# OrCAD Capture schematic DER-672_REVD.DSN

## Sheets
1 PAGE1: size Custom; title: DER-672; rev: D
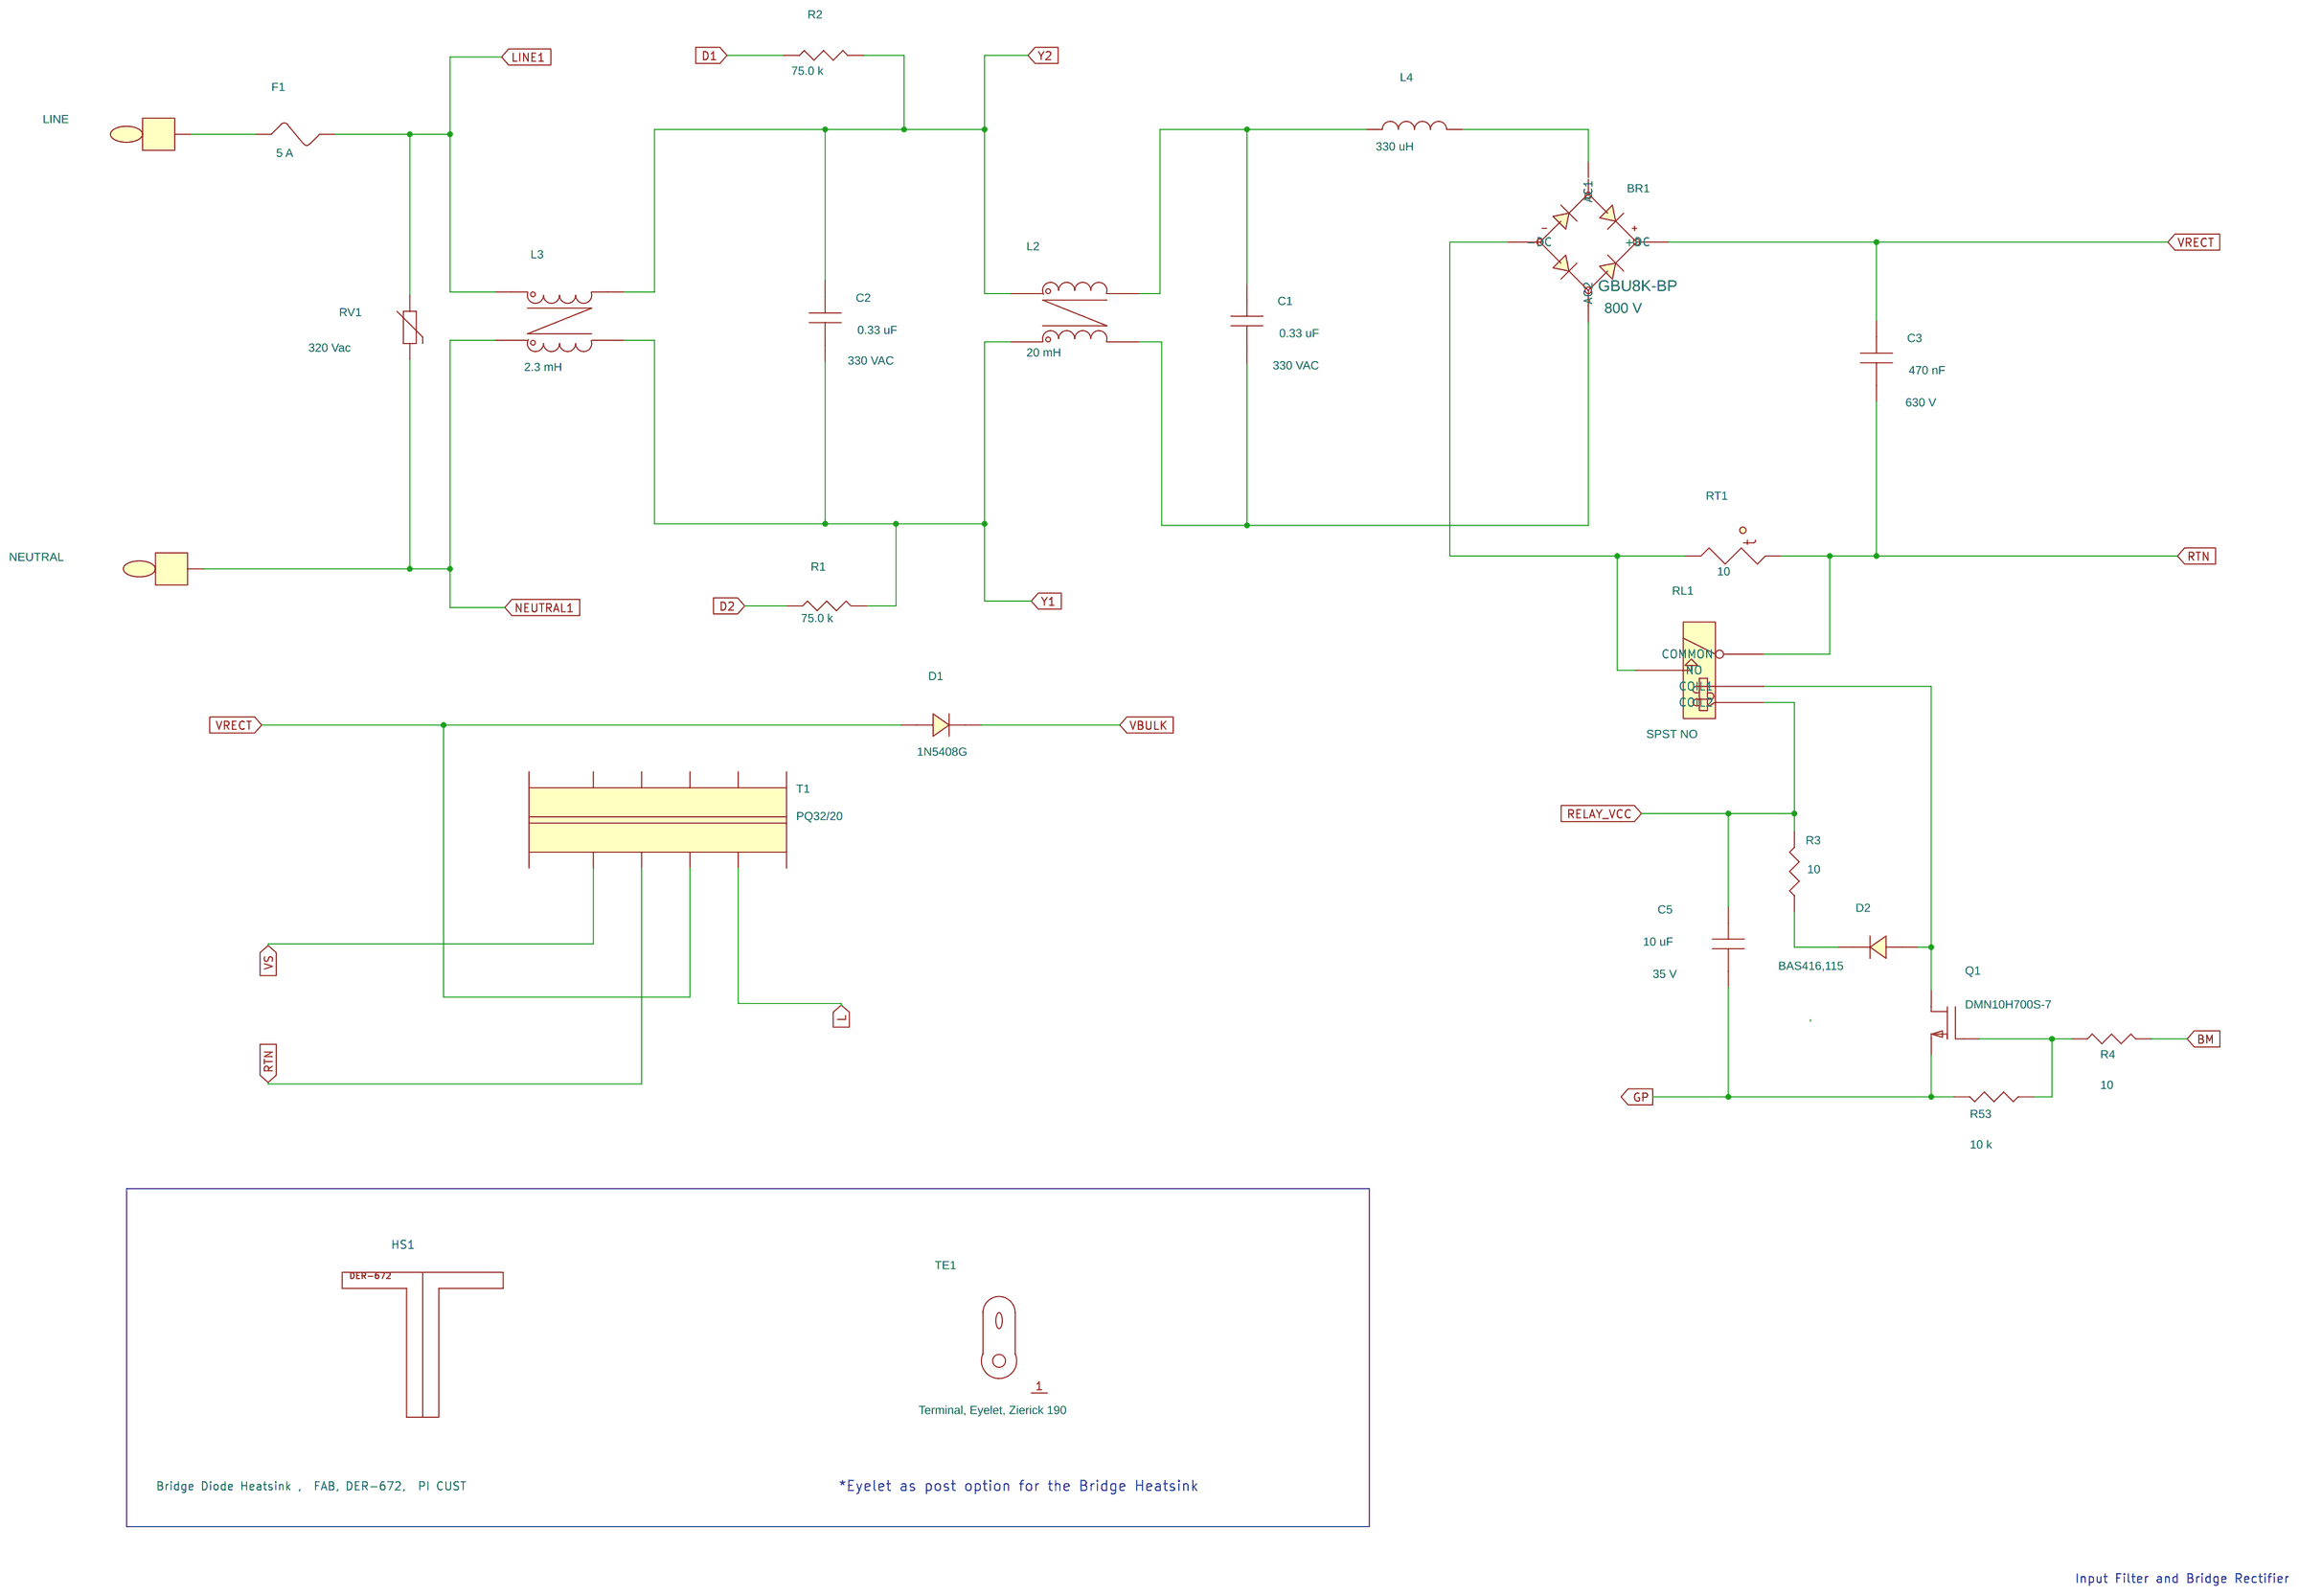
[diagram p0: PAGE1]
2 PAGE2: size B
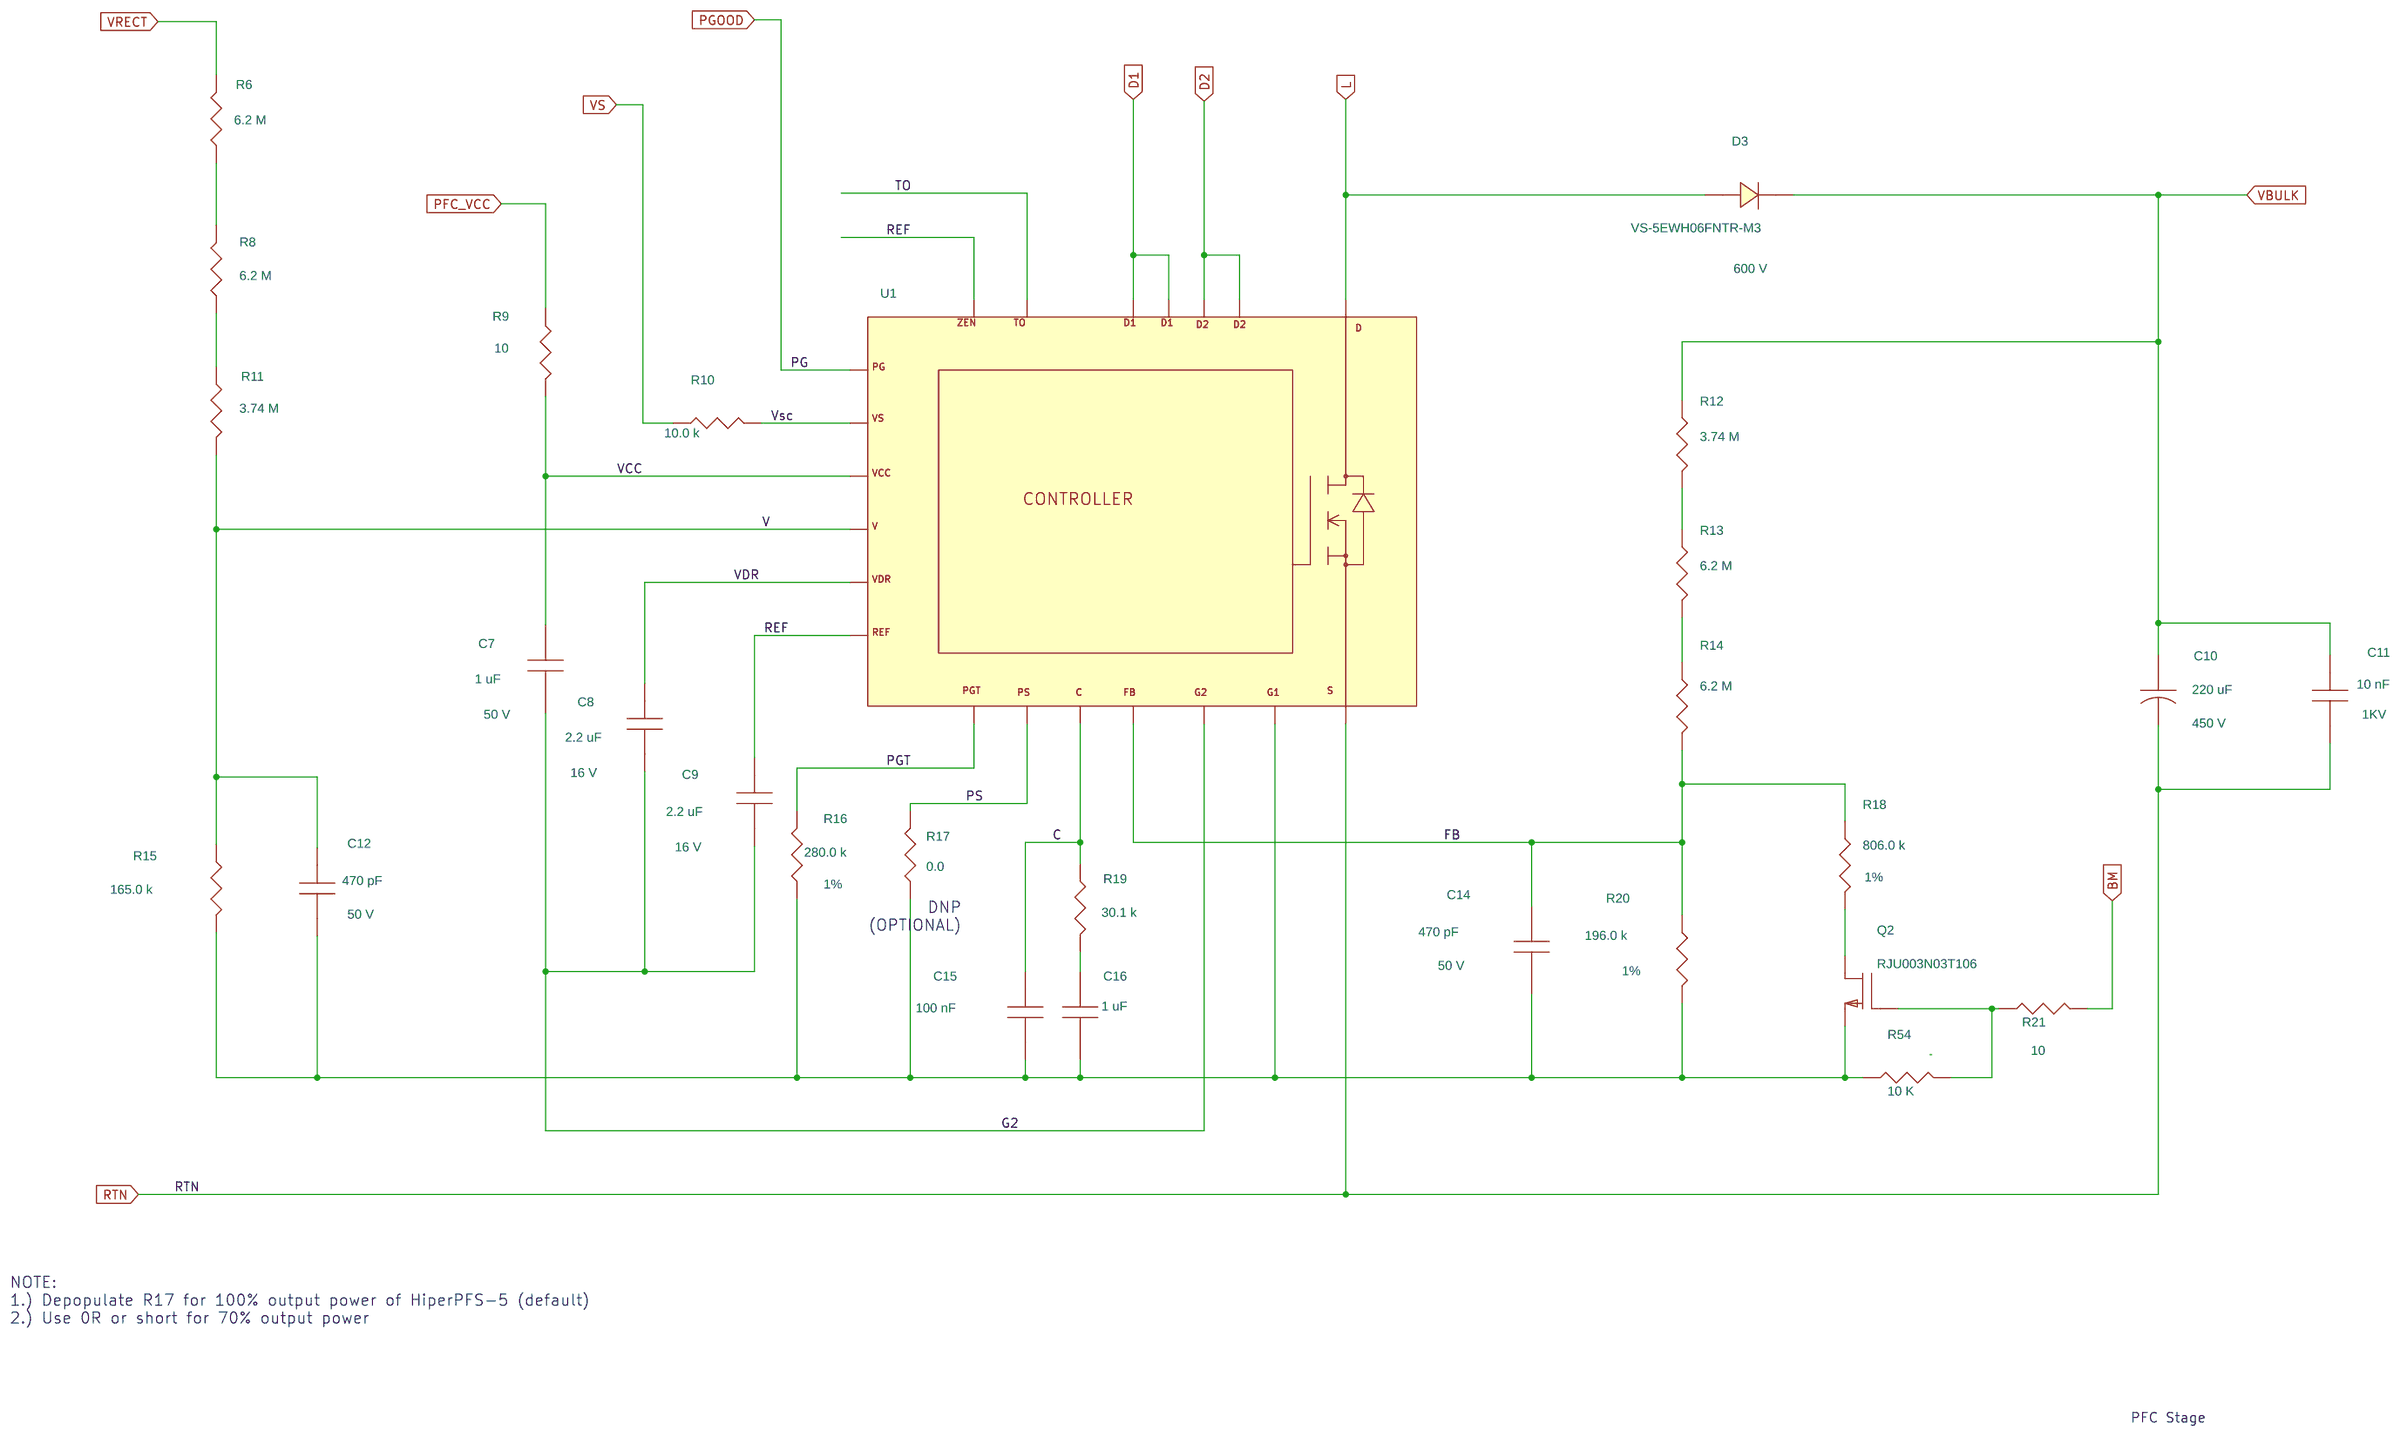
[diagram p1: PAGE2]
3 PAGE3: size Custom
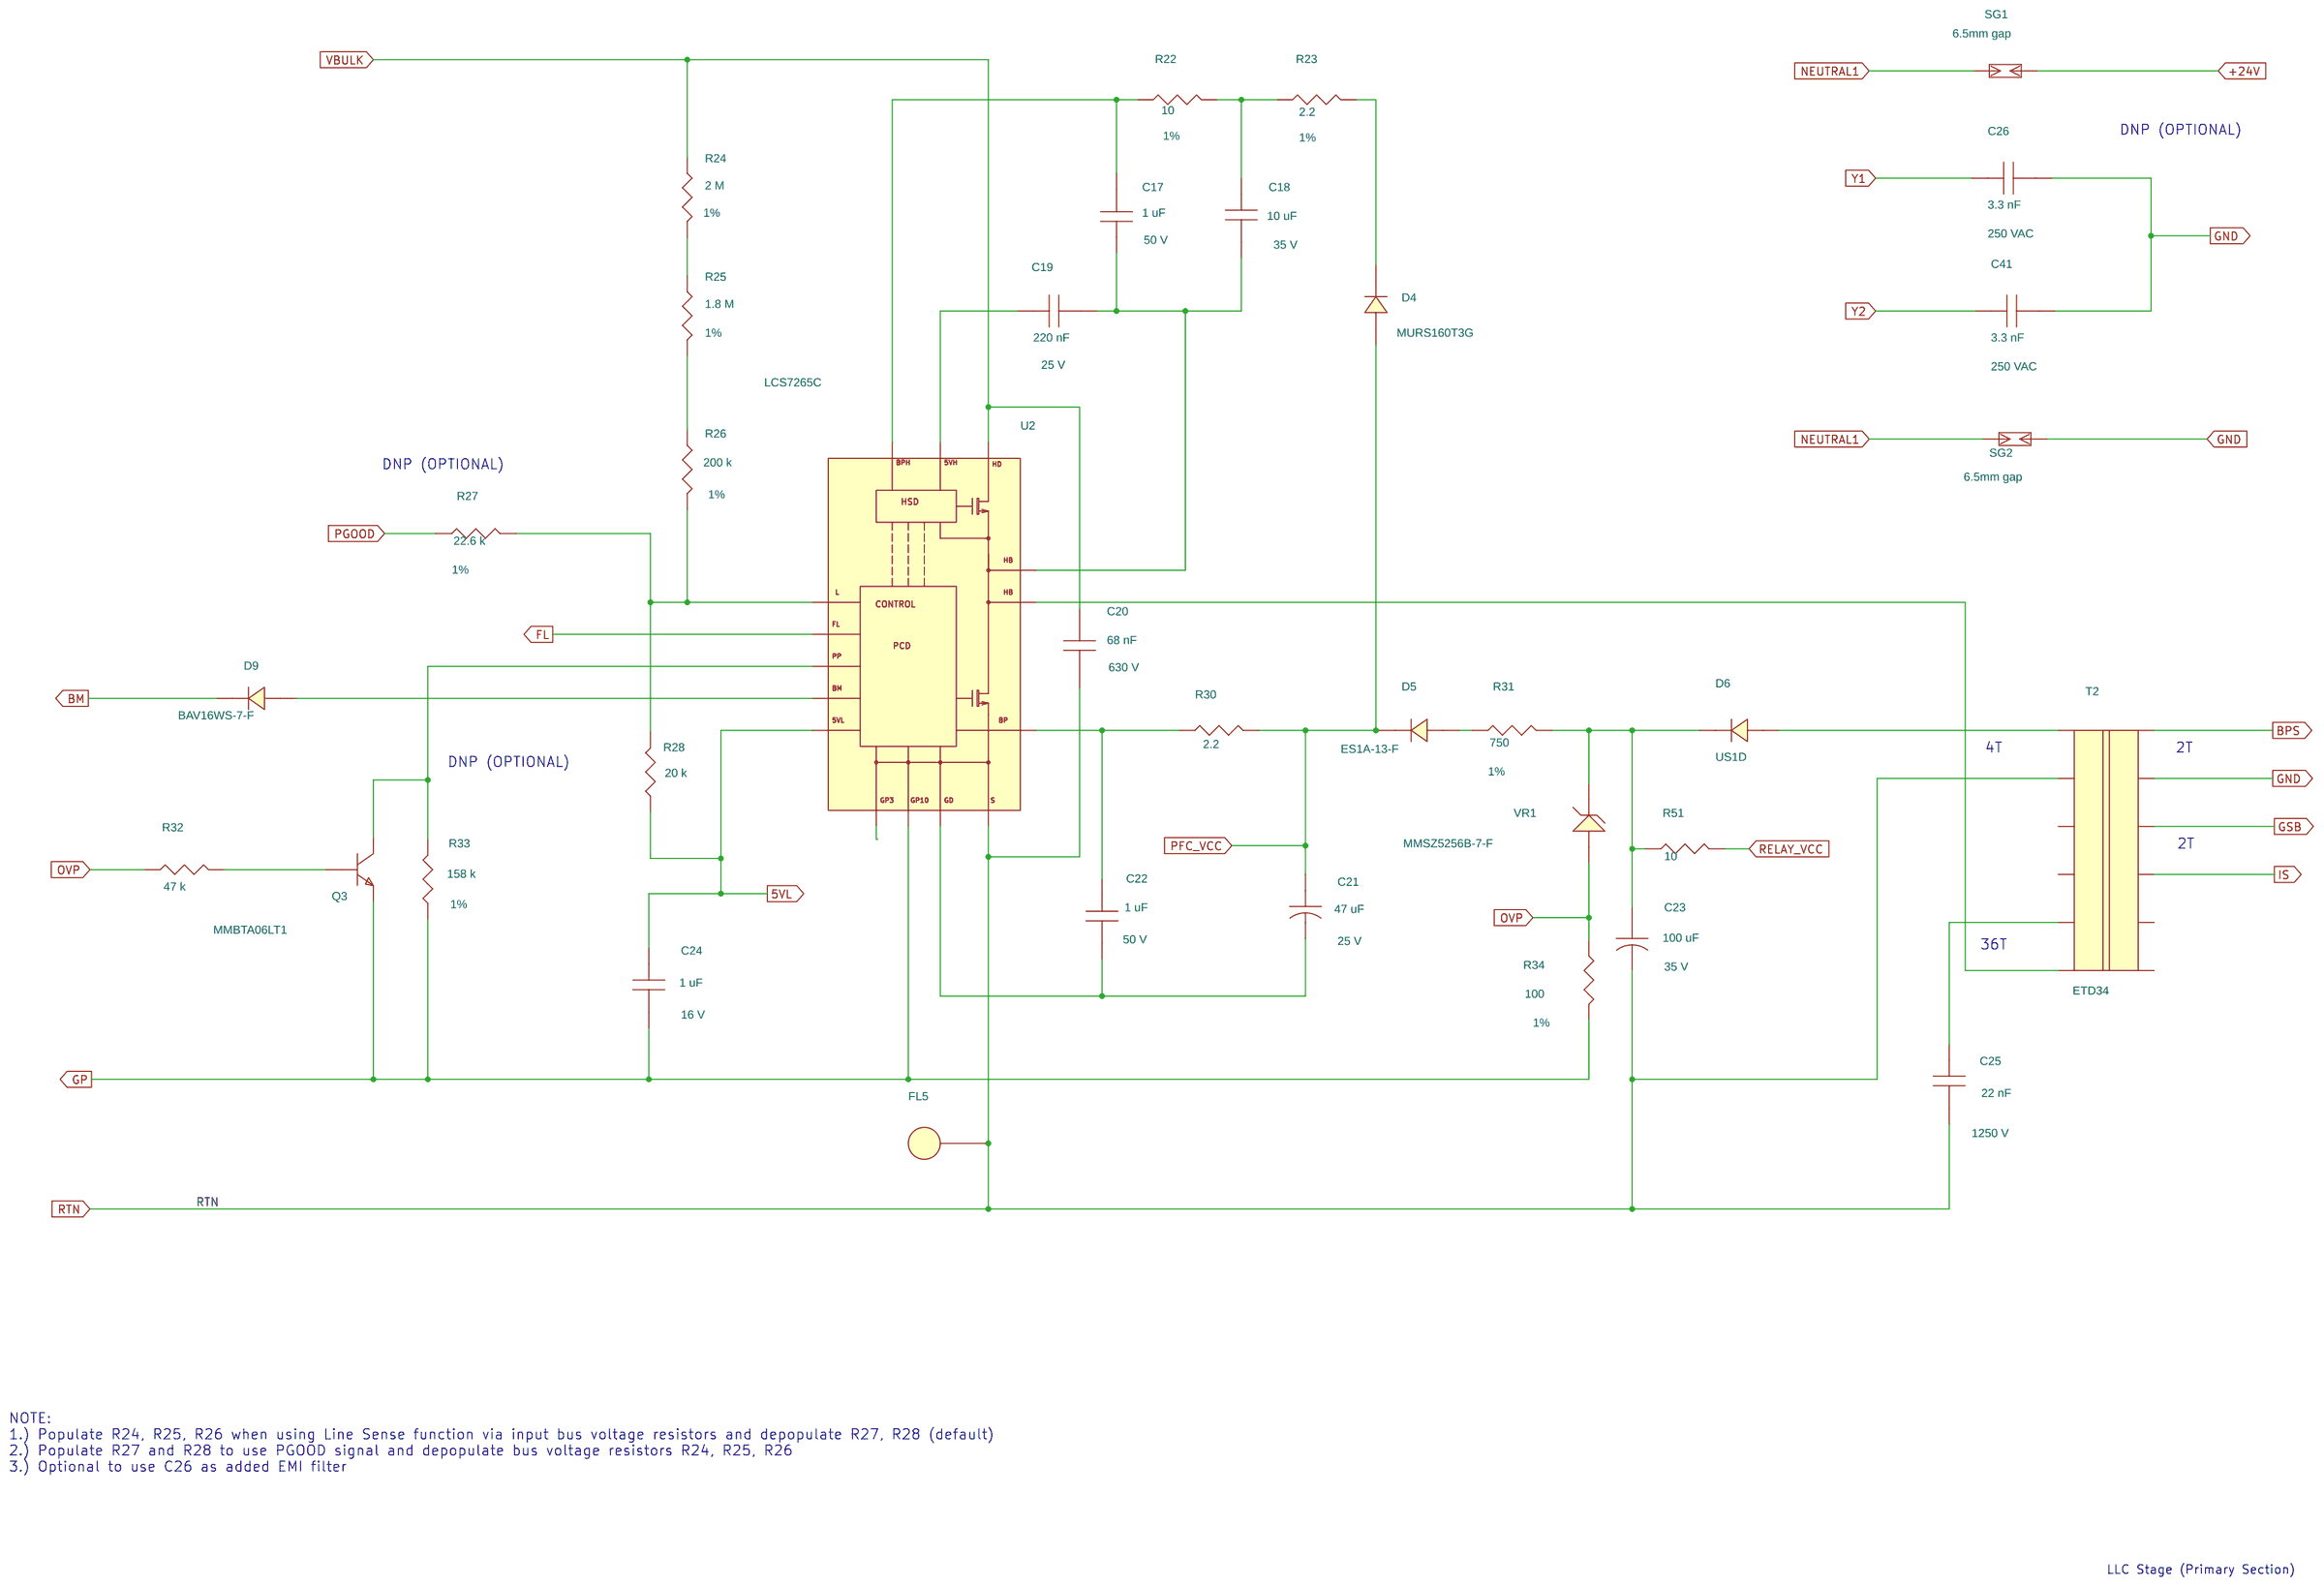
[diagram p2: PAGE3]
4 PAGE4: size Custom
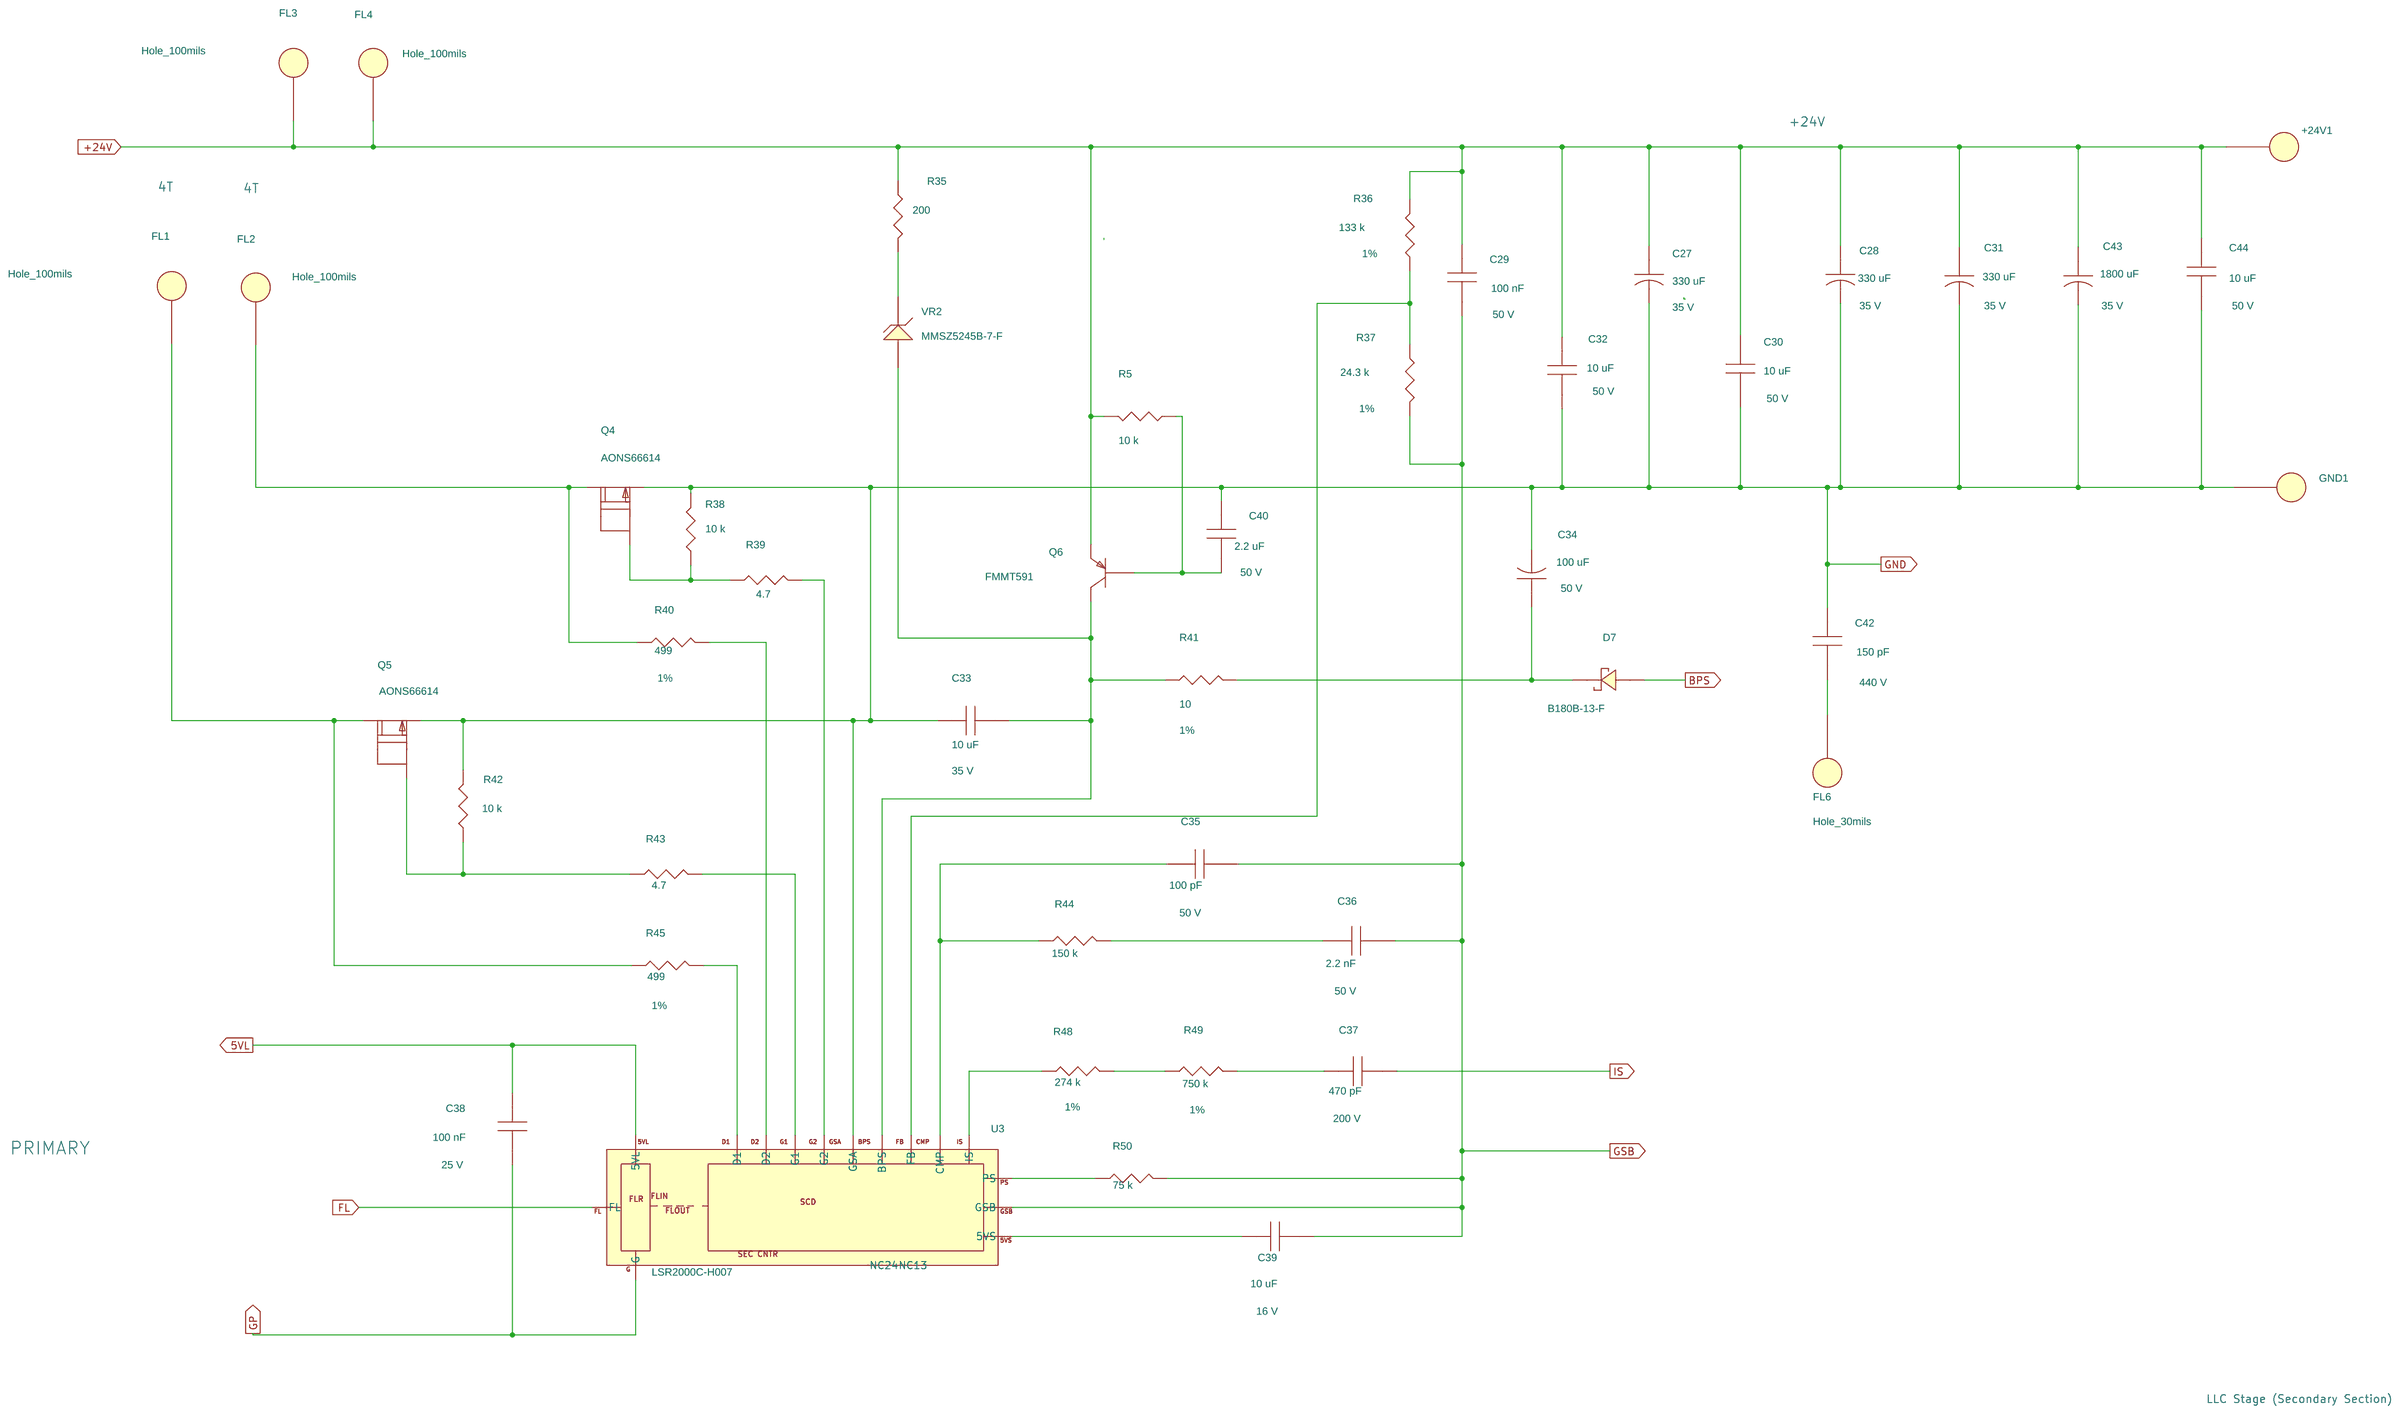
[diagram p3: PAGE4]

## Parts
sheet PAGE1
BR1  GBU8K-BP  [pidaxbridgegbu8]
C1  0.33 uF  [pi_np_caprad709x354ls590d050]
C2  0.33 uF  [pi_np_caprad709x354ls590d050]
C3  470 nF  [pinpcaprad760x450675040]
C5  10 uF  [pismc0805]
D1  1N5408G  [pidv300x200x060do15d0201ad]
D2  BAS416,115  [pismdsod323]
F1  5 A  [pi_tr5_submin_fuse]
HS1  Bridge Diode Heatsink ,  FAB, DER-672,  PI CUST  [PI_hs_0P_Bridge_DER-672]
L2  20 mH  [pi4p28x19p5x20lsd60]
L3  2.3 mH  [pi4p21p7x11p5d60]
L4  330 uH  [pi_toroid_2p_550x950_ls480_d050]
LINE  WHT  [pitpkeystone125x125]
NEUTRAL  YEL  [pitpkeystone125x125]
Q1  DMN10H700S-7  [pismsot23123_1]
R1  75.0 k  [pismr1206]
R2  75.0 k  [pismr1206]
R3  10  [pismr0603]
R4  10  [pismr0603]
R53  10 k  [pismr0603]
RL1  SPST NO  [pi_relay1]
RT1  10  [pi_rad770x220ls330d052]
RV1  320 Vac  [pidisc675x225ls335x140040]
T1  PQ32/20  [pi_bobbin_bpq32_20_12p]
TE1  Terminal, Eyelet, Zierick 190  [pi_zierick190_eyelet]
sheet PAGE2
C7  1 uF  [pismc0603]
C8  2.2 uF  [pismc0402]
C9  2.2 uF  [pismc0402]
C10  220 uF  [pipolcapclyd25mm10mmls080]
C11  10 nF  [pismc1812]
C12  470 pF  [pismr0402]
C14  470 pF  [pismr0402]
C15  100 nF  [pismr0402]
C16  1 uF  [pismr0402]
D3  VS-5EWH06FNTR-M3  [pi_sm_to252_dpak]
Q2  RJU003N03T106  [pismsot323]
R6  6.2 M  [pismr1206]
R8  6.2 M  [pismr1206]
R9  10  [pismr0603]
R10  10.0 k  [pismr0402]
R11  3.74 M  [pismr1206]
R12  3.74 M  [pismr1206]
R13  6.2 M  [pismr1206]
R14  6.2 M  [pismr1206]
R15  165.0 k  [pismr0402]
R16  280.0 k  [pismr0402]
R17  0.0  [pismr0402]
R18  806.0 k  [pismr0402]
R19  30.1 k  [pismr0402]
R20  196.0 k  [pismr0402]
R21  10  [pismr0603]
R54  10 K  [pismr0402]
U1  PFGCZ  [inSOP-T28F]
sheet PAGE3
C17  1 uF  [pismc0805]
C18  10 uF  [pismc0805]
C19  220 nF  [pismc0805]
C20  68 nF  [pinpcaprad760x250590040]
C21  47 uF  [pipolcapclyd200ls80030]
C22  1 uF  [pismc0805]
C23  100 uF  [pipolcapcyld250ls100030]
C24  1 uF  [pismc0603]
C25  22 nF  [pinpxcaprad720x340590040]
C26  3.3 nF  [pinpycaprad540x290ls400040]
C41  3.3 nF  [pinpycaprad540x290ls400040]
D4  MURS160T3G  [pismsmb]
D5  ES1A-13-F  [pismdo214ac12]
D6  US1D  [pismdsma]
D9  BAV16WS-7-F  [pismsod323]
FL5  Hole_30mils  [pi_hole_30mil]
Q3  MMBTA06LT1  [pismsot23123_1]
R22  10  [pismr0603]
R23  2.2  [pismr0603]
R24  2 M  [pismr0805]
R25  1.8 M  [pismr0805]
R26  200 k  [pismr0805]
R27  22.6 k  [pismr0603]
R28  20 k  [pismr0603]
R30  2.2  [pismr0805]
R31  750  [pismr1206]
R32  47 k  [pismr0603]
R33  158 k  [pismr0603]
R34  100  [pismr0603]
R51  10  [pismr1206]
SG1  6.5mm gap  [PI_SPARK_GAP_6p5MM]
SG2  6.5mm gap  [PI_SPARK_GAP_6p5MM]
T2  ETD34  [pi_bobbin_etd34_12p_cutout]
U2  LCS7265C  [pi_ic_insop_24C_1]
VR1  MMSZ5256B-7-F  [pi_sm_sod-123_12]
sheet PAGE4
+24V1  Hole_100mils  [pi_hole_100mil]
C27  330 uF  [pipolcapcyld400ls200040]
C28  330 uF  [pipolcapcyld400ls200040]
C29  100 nF  [pismc0603]
C30  10 uF  [pismc1206]
C31  330 uF  [pipolcapcyld400ls200040]
C32  10 uF  [pismc1206]
C33  10 uF  [pismc0805]
C34  100 uF  [pipolcapclyd320ls140030]
C35  100 pF  [pismc0603]
C36  2.2 nF  [pismc0603]
C37  470 pF  [pismc0805]
C38  100 nF  [pismc0603]
C39  10 uF  [pismc0805]
C40  2.2 uF  [pismc0805]
C42  150 pF  [pinpcaprad6p5x5p5x10mmlsd030]
C43  1800 uF  [pipolcapclyd630ls300040]
C44  10 uF  [pismc1206]
D7  B180B-13-F  [pismdo214aa12]
FL1  Hole_100mils  [pi_hole_100mil]
FL2  Hole_100mils  [pi_hole_100mil]
FL3  Hole_100mils  [pi_hole_100mil]
FL4  Hole_100mils  [pi_hole_100mil]
FL6  Hole_30mils  [pi_hole_30mil]
GND1  Hole_100mils  [pi_hole_100mil]
Q4  AONS66614  [pismpqfn5x6b]
Q5  AONS66614  [pismpqfn5x6b]
Q6  FMMT591  [pismsot23123_1]
R5  10 k  [pismr0603]
R35  200  [pismr0805]
R36  133 k  [pismr0603]
R37  24.3 k  [pismr0603]
R38  10 k  [pismr0603]
R39  4.7  [pismr0603]
R40  499  [pismr0603]
R41  10  [pismr1206]
R42  10 k  [pismr0603]
R43  4.7  [pismr0603]
R44  150 k  [pismr0603]
R45  499  [pismr0603]
R48  274 k  [pismr0603]
R49  750 k  [pismr0805]
R50  75 k  [pismr0603]
U3  LSR2000C-H007  [pi_ic_insop_24D]
VR2  MMSZ5245B-7-F  [pi_sm_sod-123_12]

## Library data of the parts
BR1 = DISCRETE_BRIDGE_+~~-: ALT_SYMBOLS: pidaxbridgegbu8_horz; Disp_Voltage: 800 V; FPLIST: pidaxbridgegbu8,pidaxbridgegbu8_horz; Part Number: 15-00347-00
C1 C2 = CAP_NP: Disp_Voltage: 330 VAC; Part Number: 20-08966-00; Voltage: 330 VAC
C3 = CAP_NP: Disp_Voltage: 630 V; Part Number: 20-00765-00; Voltage: 630 V
C5 C18 C33 = CAP_NP: ALT_SYMBOLS: Unisem_RMCF0805UL,CC0805,pismc0805_1; Disp_Voltage: 35 V; FPLIST: pismc0805,Unisem_RMCF0805UL,CC0805,pismc0805_1; Part Number: 20-01692-00; Voltage: 35 V
D1 = DIODE: ALT_SYMBOLS: pidv300x472x060do14wbead,pidax800x225060do15do201ad,pidv300x200x060do14wbead; FPLIST: pidv300x200x060do15d0201ad,pidv300x472x060do14wbead,pidax800x225060do15do201ad,pidv300x200x060do14wbead; Part Number: 15-01651-00
D2 = DIODE: Part Number: 15-01164-00
F1 = FUSE: Part Number: 40-00005-00
HS1 = hs_0P_Bridge_DER672: Part Number: 61-00318-01
L2 = TORRID_4P_14_23: Part Number: 32-00436-00
L3 = TORRID_4P_14_23: Part Number: 32-00437-00
L4 = INDUCTOR: Part Number: 32-00295-00
LINE = TESTPOINT: Part Number: 35-00044-00
NEUTRAL = TESTPOINT: Part Number: 35-00046-00
Q1 = FET_N_GSD: Part Number: 50-00416-00
R1 R2 = R: Disp_Tol: 1%; Part Number: 05-00373-00
R3 R4 R9 R21 = R: Disp_Tol: 1%; Part Number: 05-00886-00; ROOM: 2
R5 R38 R42 R53 = R: Part Number: 05-01712-00; ROOM: 2
RL1 = RELAY_SPST_NO_1634: Part Number: 66-00378-00
RT1 = THERMISTOR: Part Number: 90-00019-00
RV1 = VARISTOR: Part Number: 85-00009-00
T1 = BPQ32_20_12P_GENERIC: Part Number: 25-00077-00
TE1 = TERM_EYLT: Part Number: 60-00016-00
C7 = CAP_NP: Disp_Voltage: 50 V; Part Number: 20-09159-00; ROOM: 2; Voltage: 50 V
C8 C9 = CAP_NP: ALT_SYMBOLS: pismr0402_1; Disp_Voltage: 16 V; FPLIST: pismc0402,pismr0402_1; Part Number: 20-09202-00; ROOM: 2; Voltage: 16 V
C10 = CAP_POL: ALT_SYMBOLS: pipcap25h40x10mmls080H; Disp_Voltage: 450 V; FPLIST: pipolcapclyd25mm10mmls080,pipcap25h40x10mmls080H; Part Number: 20-01767-00; Voltage: 450 V
C11 = CAP_NP: Disp_Voltage: 1KV; Part Number: 20-00846-00; Voltage: 1KV
C12 C14 = CAP_NP: ALT_SYMBOLS: pismr0402_1; Disp_Voltage: 50 V; FPLIST: pismr0402,pismr0402_1; Part Number: 20-09060-00; ROOM: 2; Voltage: 50 V
C15 = CAP_NP: ALT_SYMBOLS: pismr0402_1; Disp_Voltage: 16 V; FPLIST: pismr0402,pismr0402_1; Part Number: 20-08759-00; ROOM: 2; Voltage: 16 V
C16 = CAP_NP: ALT_SYMBOLS: pismr0402_1; Disp_Voltage: 25 V; FPLIST: pismr0402,pismr0402_1; Part Number: 20-09151-00; ROOM: 2; Voltage: 25 V
D3 = DIODE_DPAK: Disp_Voltage: 600 V; Part Number: 15-01746-00
Q2 = FET_N_SGD: Part Number: 50-00177-00
R6 R8 R13 = R: Part Number: 05-01440-00; ROOM: 2
R10 = R: ALT_SYMBOLS: pismr0402_1; Disp_Tol: 1%; FPLIST: pismr0402,pismr0402_1; Part Number: 05-05935-00; ROOM: 2
R11 R12 = R: Part Number: 05-05572-00; ROOM: 2
R14 = R: Disp_Tol: 1%; Part Number: 05-05567-00; ROOM: 2
R15 = R: Disp_Tol: 1%; Part Number: 05-06059-00; ROOM: 2
R16 = R: Disp_Tol: 1%; Part Number: 05-06083-00; ROOM: 2
R17 = R: Part Number: 05-06420-00; ROOM: 2
R18 = R: Disp_Tol: 1%; Part Number: 05-06136-00; ROOM: 2
R19 = R: Disp_Tol: 1%; Part Number: 05-05984-00; ROOM: 2
R20 = R: Disp_Tol: 1%; Part Number: 05-06065-00; ROOM: 2
R54 = R: Part Number: 05-03488-00; ROOM: 2
U1 = PFSGaN_InSOP-T28F28: Part Number: 10-01271-00
C17 = CAP_NP: Disp_Voltage: 50 V; Part Number: 20-09156-00; Voltage: 50 V
C19 = CAP_NP: Disp_Voltage: 25 V; Part Number: 20-00237-00; Voltage: 25 V
C20 = CAP_NP: Disp_Voltage: 630 V; Part Number: 20-00399-00; Voltage: 630 V
C21 = CAP_POL: ALT_SYMBOLS: pipolcapclyd200ls80030h; Disp_Voltage: 25 V; FPLIST: pipolcapclyd200ls80030,pipolcapclyd200ls80030h; Part Number: 20-00026-00; Voltage: 25 V
C22 = CAP_NP: Disp_Voltage: 50 V; Part Number: 20-09156-00; ROOM: 1; Voltage: 50 V
C23 = CAP_POL: ALT_SYMBOLS: pipolcapclyd250ls100d30h590; Disp_Voltage: 35 V; FPLIST: pipolcapcyld250ls100030,pipolcapclyd250ls100d30h590; Part Number: 20-00117-00; Voltage: 35 V
C24 = CAP_NP: Disp_Voltage: 16 V; Part Number: 20-01020-00; ROOM: 1; Voltage: 16 V
C25 = CAP_NP: Disp_Voltage: 1250 V; Part Number: 20-00722-00; Voltage: 1250 V
C26 C41 = CAP_NP: ALT_SYMBOLS: pinpycaprad540x290ls400040h; Disp_Voltage: 250 VAC; FPLIST: pinpycaprad540x290ls400040,pinpycaprad540x290ls400040h; Part Number: 20-00377-00; Voltage: 250 VAC
D4 = DIODE: Part Number: 15-00487-00; ROOM: 1
D5 = DIODE: Part Number: 15-00351-00
D6 = DIODE: Part Number: 15-00492-00
D9 = DIODE: Part Number: 15-00850-00; ROOM: 1
FL5 FL6 = FlyingLead: Part Number: 35-00284-00
Q3 = NPN_BEC: Part Number: 55-00030-00
R22 = R: Disp_Tol: 1%; Part Number: 05-00886-00
R23 = R: Disp_Tol: 1%; Part Number: 05-01278-00
R24 = R: Disp_Tol: 1%; Part Number: 05-00883-00; ROOM: 1
R25 = R: Disp_Tol: 1%; Part Number: 05-00882-00; ROOM: 1
R26 = R: ALT_SYMBOLS: Unisem_RMCF0805UL; Disp_Tol: 1%; FPLIST: pismr0805,Unisem_RMCF0805UL; Part Number: 05-00809-00
R27 = R: Disp_Tol: 1%; Part Number: 05-03218-00; ROOM: 1
R28 = R: Part Number: 05-01719-00; ROOM: 1
R30 = R: Part Number: 05-01455-00
R31 = R: Disp_Tol: 1%; Part Number: 05-00181-00
R32 = R: Part Number: 05-01728-00
R33 = R: Disp_Tol: 1%; Part Number: 05-01193-00; ROOM: 1
R34 = R: Disp_Tol: 1%; Part Number: 05-06490-00
R41 R51 = R: Disp_Tol: 1%; Part Number: 05-00001-00
SG1 SG2 = SPARK_GAP: Part Number: 66-00355-00
T2 = BETD34_12P_GENERIC: Part Number: 25-01048-00
U2 = HiperLCS-SR_A_INSOP24C_5: Part Number: 10-01120-00
VR1 = DIODE_ZENER: Part Number: 15-01096-00
+24V1 FL1-FL4 GND1 = FlyingLead: Part Number: 35-00432-00; ROOM: 2
C27 C28 C31 = CAP_POL: Disp_Voltage: 35 V; Part Number: 20-01364-00; Voltage: 35 V
C29 = CAP_NP: Disp_Voltage: 50 V; Part Number: 20-01693-00; Voltage: 50 V
C30 C32 C44 = CAP_NP: ALT_SYMBOLS: pismc1206_1; Disp_Voltage: 50 V; FPLIST: pismc1206,pismc1206_1; Part Number: 20-08995-00; Voltage: 50 V
C34 = CAP_POL: ALT_SYMBOLS: pipolcapclyd320ls140030430h; Disp_Voltage: 50 V; FPLIST: pipolcapclyd320ls140030,pipolcapclyd320ls140030430h,pipolcapclyd320ls140030430h; Part Number: 20-00058-00; Voltage: 50 V
C35 = CAP_NP: Disp_Voltage: 50 V; Part Number: 20-01025-00; ROOM: 2; Voltage: 50 V
C36 = CAP_NP: Disp_Voltage: 50 V; Part Number: 20-08677-00; ROOM: 2; Voltage: 50 V
C37 = CAP_NP: Disp_Voltage: 200 V; Part Number: 20-01187-00; ROOM: 2; Voltage: 200 V
C38 = CAP_NP: Disp_Voltage: 25 V; Part Number: 20-00528-00; Voltage: 25 V
C39 = CAP_NP: ALT_SYMBOLS: Unisem_RMCF0805UL; Disp_Voltage: 16 V; FPLIST: pismc0805,Unisem_RMCF0805UL; Part Number: 20-08964-00; Voltage: 16 V
C40 = CAP_NP: Disp_Voltage: 50 V; Part Number: 20-09011-00; ROOM: 2; Voltage: 50 V
C42 = CAP_NP: Disp_Voltage: 440 V; Part Number: 20-02055-00; Voltage: 440 V
C43 = CAP_POL: ALT_SYMBOLS: pipolcapclyd630ls3000401000h; Disp_Voltage: 35 V; FPLIST: pipolcapclyd630ls300040,pipolcapclyd630ls3000401000h; Part Number: 20-00055-00; Voltage: 35 V
D7 = DIODE_SCHOTTKY: Part Number: 15-00679-00
Q4 Q5 = FET_N_SGD_123_4_5678: Part Number: 50-00380-00
Q6 = PNP_BEC: Part Number: 55-00047-00
R35 = R: ALT_SYMBOLS: pismr0805_1; FPLIST: pismr0805,pismr0805_1; Part Number: 05-01502-00
R36 = R: Disp_Tol: 1%; Part Number: 05-01186-00; ROOM: 2
R37 = R: Disp_Tol: 1%; Part Number: 05-03221-00; ROOM: 2
R39 R43 = R: Part Number: 05-01632-00
R40 R45 = R: Disp_Tol: 1%; Part Number: 05-01049-00
R44 = R: Disp_Tol: 1%; Part Number: 05-01191-00; ROOM: 2
R48 = R: Disp_Tol: 1%; Part Number: 05-01216-00; ROOM: 2
R49 = R: Disp_Tol: 1%; Part Number: 05-00864-00; ROOM: 2
R50 = R: Part Number: 05-01733-00; ROOM: 2
U3 = HiperLCS2-SR: Part Number: 10-01122-07
VR2 = DIODE_ZENER: Part Number: 15-01091-00

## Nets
5VL: C24.1 C38.1 R28.1 U2.6 U3.15(5VL)
+24V: +24V1.1 C27.1 C28.1 C29.1 C30.1 C31.1 C32.1 C43.1 C44.1 FL3.1 FL4.1 Q6.2(EMITTER) R5.2 R35.1 R36.1 SG1.2
GND: C26.2 C27.2 C28.2 C30.2 C31.2 C32.2 C33.1 C34.2 C40.1 C41.2 C42.1 C43.2 C44.2 GND1.1 Q4.1(S) Q5.1(S) R38.1 R42.1 SG2.2 T2.5 U3.12(GSA)
VCC: C7.1 R9.2 U1.14
BM: D9.1 R4.1 R21.1
BPS: D7.2 T2.6
C: C15.1 R19.1 U1.5
D1: R2.1 U1.15 U1.16
D2: R1.1 U1.18 U1.19
FB: C14.1 R14.1 R18.2 R20.2 U1.6
FL: U2.7 U3.14(FL)
G2: C7.2 C8.2 C9.2 U1.13
GP: C5.2 C24.2 C38.2 Q1.2(S) Q3.2(EMITTER) R33.2 R34.2 R53.1 U2.10 U3.16(G)
GSB: C29.2 C35.2 C36.2 C39.2 R37.2 R50.2 T2.4 U3.2(GSB)
IS: C37.2 T2.3
L: D3.3 T1.5 U1.28
LINE1: F1.2 L3.1 RV1.1
NEUTRAL1: L3.2 NEUTRAL.1 RV1.2 SG1.1 SG2.1
OVP: R32.1 R34.1 VR1.2
PFC_VCC: C21.1 D4.2 D5.1 R9.1 R30.2
PGOOD: R27.1 U1.7
PGT: R16.2 U1.8
PS: R17.2 U1.9
REF: C9.1 U1.10 U1.11
RELAY_VCC: C5.1 R3.1 R51.2 RL1.6(COIL2)
RTN: C3.2 C10.2 C11.2 C20.2 C23.2 C25.2 FL5.1 RL1.3(COMMON) RT1.2 T1.3 T2.8 U1.21 U2.24
TO: U1.3
V: C12.1 R11.2 R15.1 U1.4
VBULK: C10.1 C11.1 C20.1 D1.1 D3.2 R12.1 R24.1 U2.25
VDR: C8.1 U1.12
VRECT: BR1.1(+DC) C3.1 D1.2 R6.2 T1.4
VS: R10.1 T1.2
Vsc: R10.2 U1.1
Y1: C2.2 C26.1 L2.1 L3.3 R1.2
Y2: C2.1 C41.1 L2.2 L3.4 R2.2
N4285050: C17.1 C18.2 C19.2 U2.16
N4286456: C19.1 U2.14
N4286477: C17.2 R22.1 U2.15
N4286493: D4.1 R23.2
N4298336: D6.2 T2.7
N4342721: C23.1 D6.1 R31.2 R51.1 VR1.1
N4344251: Q3.3(COLLECTOR) R33.1 U2.8
N4345605: C21.2 C22.2 U2.1
N4347891: C22.1 R30.1 U2.5
N4369156: R36.2 R37.1 U3.5(FB)
N4369530: C35.1 R44.1 U3.4(CMP)
N4369660: R48.2 U3.3(IS)
N4369788: C39.1 U3.1(5VS)
N4383576: R43.2 U3.9(G1)
N4398139: FL2.1 Q4.5(D) R40.1
N4399978: FL1.1 Q5.5(D) R45.1
N4403558: Q4.4(G) R38.2 R39.1
N4403571: R39.2 U3.8(G2)
N4411199: R48.1 R49.1
N4411203: C37.1 R49.2
N4415619: C36.1 R44.2
N4433947: Q5.4(G) R42.2 R43.1
N4462598: C33.2 Q6.3(COLLECTOR) R41.1 U3.7(BPS) VR2.2
N4490514: C25.1 T2.11
N4535120: R26.2 R27.2 R28.2 U2.12
N11926581: R50.1 U3.6(PS)
N12003586: Q3.1(BASE) R32.2
N12130188: R45.2 U3.11(D1)
N12130239: R40.2 U3.10(D2)
N12141521: T2.12 U2.19
N12150808: C18.1 R22.2 R23.1
N12190763: C34.1 D7.1 R41.2
N12204254: C1.1 L2.3 L4.2
N12204372: BR1.4(-DC) RL1.4(NO) RT1.1
N12204532: BR1.3(AC2) C1.2 L2.4
N12221428: R6.1 R8.2
N12221554: R8.1 R11.1
N12221692: R12.2 R13.1
N12221812: R13.2 R14.2
N12221868: C12.2 C14.2 C15.2 C16.2 Q2.1(S) R15.2 R16.1 R17.1 R20.1 R54.2 U1.2
N12222300: C16.1 R19.2
N12229995: D5.2 R31.1
N12233962: Q2.3(D) R18.1
N12234276: Q2.2(G) R21.2 R54.1
N12240068: Q1.1(G) R4.2 R53.2
N12240080: D2.2 Q1.3(D) RL1.1(COIL1)
N12240868: D2.1 R3.2
N12267959: C40.2 Q6.1(BASE) R5.1
N12332190: R24.2 R25.1
N12332212: R25.2 R26.1
N12355111: R35.2 VR2.1
N12418022: D9.2 U2.2
N12546912: BR1.2(AC1) L4.1
N12560254: C42.2 FL6.1
N12565241: F1.1 LINE.1

Not connected (* = marked no-connect by the designer): Q4 2(S2) 3(S3) 6(D6) 7(D7) 8(D8); Q5 2(S2) 3(S3) 6(D6) 7(D7) 8(D8); T1 1 6 7 8 9 10 11 12; T2 1 2 9 10; TE1 1; U2 3; U3 13(NC13) 24(NC24)

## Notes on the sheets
sheet 1
- *Eyelet as post option for the Bridge Heatsink
- Input Filter and Bridge Rectifier
sheet 2
- DNP
  (OPTIONAL)
- NOTE:
  1.) Depopulate R17 for 100% output power of HiperPFS-5 (default)
  2.) Use 0R or short for 70% output power
- PFC Stage
sheet 3
- DNP (OPTIONAL)
- DNP (OPTIONAL)
- 4T
- 2T
- DNP (OPTIONAL)
- 2T
- 36T
- NOTE:
  1.) Populate R24, R25, R26 when using Line Sense function via input bus voltage resistors and depopulate R27, R28 (default)
  2.) Populate R27 and R28 to use PGOOD signal and depopulate bus voltage resistors R24, R25, R26
  3.) Optional to use C26 as added EMI filter
- LLC Stage (Primary Section)
sheet 4
- +24V
- 4T
- 4T
- PRIMARY
- LLC Stage (Secondary Section)
